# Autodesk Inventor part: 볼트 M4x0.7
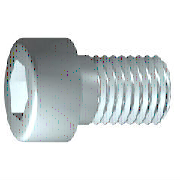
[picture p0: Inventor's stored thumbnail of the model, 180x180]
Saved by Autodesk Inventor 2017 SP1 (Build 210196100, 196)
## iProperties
IsCustomPart: 0
Created: 2015-12
Part Number: 볼트 M4x0.7
Material: 강철, 연강
Description: 6각머리 태핑 나사
Document SubType Name: Modeling
Standard: KS B 1003
Designer: mdu
Standards Organization: KS
Language: ko-KR
Size Designation: M 4 x 12
Categories: <MemberInstance><Categories><Category DisplayName="조임쇠" InternalName="e4da775c-781d-43d5-af7c-5136215cf5a6" Mnemonic="FSTN"><Category DisplayName="볼트" InternalN
Density: 7.86 g/cm^3
Appearance: 강철
Mass: 2.23465 g
Surface Area: 3.30853 cm^2
Volume: 0.284306 cm^3
Author: mdu
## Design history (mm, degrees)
sketch "스케치1"
  geometry: L1 (-1, 0)-(12, 0); L2 (12, 0)-(12, 2); L3 (12, 2)-(1.75, 2); L4 (1.75, 2)-(1.32, 2); L5 (1.32, 2)-(0, 2); L6 (0, 2)-(0, 3.5); L7 (0, 3.5)-(-4, 3.5); L8 (-4, 3.5)-(-4, 1.732); L9 (-4, 1.732)-(-2, 1.732); L10 (-2, 1.732)-(-1, 0); L11 (-7.2, 0)-(15.2, 0) reference; L12 (0, -0.7)-(0, 4.2) reference; L13 (1.75, 2)-(0, 2)
  constraints: 22 end point, 6 parallel, 2 collinear, 2 perpendicular, 1 horizontal, 1 point on line
  dimensions: "d1" = 10.25 distance from line of L3.end L2 (= GEL); "d2" = 0.42952 distance of L4.end L3.end (computed from GAL); "d3" = 4 distance between parallel lines of L8 L6 (= KOH); "d4" = 2 distance of L8.end L9.end (= INTI); "d5" = 60 deg angle of L10 L1; "d6" = 4 diameter of L3 L1 (= GD); "d7" = 4 diameter of L5 L1 (= BDM); "d8" = 3.4641 diameter of L9 L1 (= 1.1547 x SW); "d9" = 7 diameter of L7 L1 (= KOD); "d26" = 12 distance between parallel lines of L12 L2 (= NLG)
revolve "본체" sketch "스케치1" stored, may be unused: angle "d10" = 90 deg
sketch "스케치2"
  geometry: L1 (0, -4.9)-(0, 4.9) reference; L2 (-4.9, 0)-(4.9, 0) reference; L3 (1.732, 0)-(0.866, -1.5); L4 (0.866, -1.5)-(-0.866, -1.5); L5 (-0.866, -1.5)-(-1.732, 0); L6 (-1.732, 0)-(-0.866, 1.5); L7 (-0.866, 1.5)-(0.866, 1.5); L8 (0.866, 1.5)-(1.732, 0); 2 further points
  constraints: 12 end point, 1 coincident, 1 horizontal alignment, 1 point on line, 12 other
extrude "슬롯" join sketch "스케치2" stored distance "d11" = 10; taper "d12" = 0 deg
workplane "Work Plane1"
fillet "Fillet2" dims "d30" = 0.1 (= R)
body "Solid1"
fillet "모깎기1" dims "d17" = 0.4 (= RR)
feature "스레드" dims "d13" = 10.25 (= GEL), "d14" = 0
chamfer "모따기1" distance "d15" = 0.42941 (= -0.5 x SPD + 0.5 x GD); stored, may be unused: second distance "d16" = 0.42941 (= GUL), angle "d27" = 45 deg
other parameters: "GD" = 4 (= NND) [user parameter; used in 2 equation terms], "NLG" = 12 [user parameter; used in 1 equation term], "GEL" = 10.25 [user parameter; used in 2 equation terms], "KOD" = 7 [user parameter; used in 1 equation term], "KOH" = 4 [user parameter; used in 1 equation term], "INTI" = 2 [user parameter; used in 1 equation term], "GAL" = 0.42941 (= 0.61345 x PTC) [user parameter; used in 1 equation term], "GUL" = 0.42941 (= 0.61345 x PTC) [user parameter; used in 1 equation term], "BDM" = 4 (= NND) [user parameter; used in 1 equation term], "SW" = 3 [user parameter; used in 2 equation terms], "RR" = 0.4 [user parameter; used in 1 equation term], "SPD" = 3.14117 (= NND - 1.2269 x PTC) [user parameter; used in 1 equation term], "d19" = 0, "d28" = 0, "d29" = 0, "R" = 0.1 [user parameter; used in 1 equation term], "PHH" = 0.2 [user parameter], "GD1" = 3.14117 (= THREADDIA - 1.2269 x PTC) [user parameter], "THREADDIA" = 4 [user parameter; used in 1 equation term], "FAWI" = 45 deg [user parameter], "TPU" = 14.28571 (computed from PTC) [user parameter], "PTC" = 0.7 [user parameter; used in 5 equation terms], "NND" = 4 [user parameter; used in 3 equation terms], "TOA" = 30 deg [user parameter], "E0" = 3.465 (= 1.155 x SW) [user parameter]
